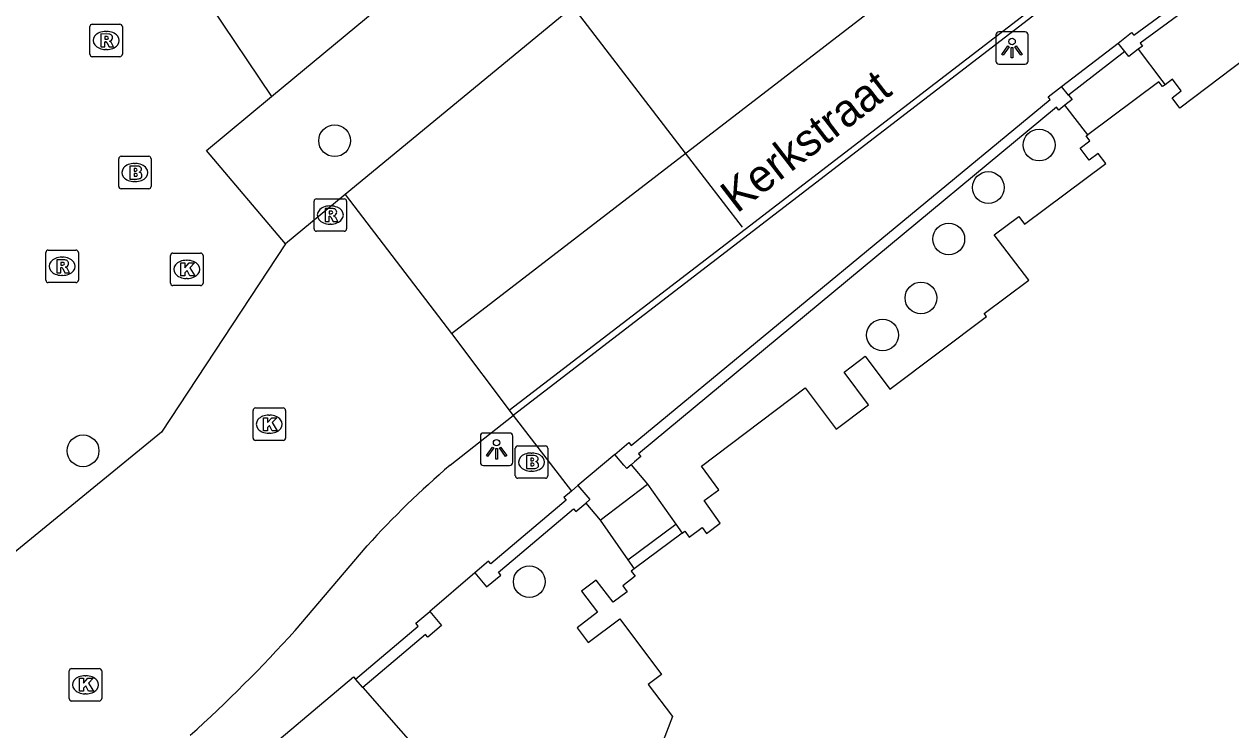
# Model space of a CAD drawing. Extents: x 161087 to 161922, y 382574 to 383873.
# Drawn here: x 161349.71 to 161386.87, y 383087.66 to 383109.41 of the extents above; entities that cross this region are included whole.
import ezdxf

# ---------------------------------------------------------------- set-up
doc = ezdxf.new("R2010")
doc.units = 0
for name, color, linetype in [('IMGEO_Boom', 7, 'Continuous'), ('IMGEO_Brandkraan', 7, 'Continuous'), ('IMGEO_Kolk', 7, 'Continuous'), ('IMGEO_Lichtpunt', 7, 'Continuous'), ('IMGEO_Lijnafwatering', 7, 'Continuous'), ('IMGEO_Muur', 7, 'Continuous'), ('IMGEO_Openbare_ruimte_label', 7, 'Continuous'), ('IMGEO_Pand', 7, 'Continuous'), ('IMGEO_Rijbaan_lokaal_open', 7, 'Continuous'), ('IMGEO_Rioolput', 7, 'Continuous'), ('IMGEO_Voetgangersgebied_open', 7, 'Continuous'), ('IMGEO_Voetpad_op_trap', 7, 'Continuous'), ('IMGEO_Voetpad_open', 7, 'Continuous')]:
    doc.layers.add(name, color=color, linetype=linetype)

msp = doc.modelspace()

# ---------------------------------------------------------------- linework, layer by layer
at = {"layer": 'IMGEO_Boom'}
for centre in [(161359.269, 383105.813), (161380.968, 383105.681), (161379.403, 383104.373), (161378.185, 383102.786), (161377.328, 383100.971), (161376.145, 383099.827), (161351.524, 383096.259), (161365.266, 383092.226)]:
    msp.add_circle(centre, 0.489, dxfattribs=at)
at = {"layer": 'IMGEO_Brandkraan'}
for p, q in [((161352.62, 383104.409), (161352.62, 383105.261)), ((161352.695, 383105.335), (161353.547, 383105.335)), ((161353.621, 383105.261), (161353.621, 383104.409)), ((161353.108, 383105.115), (161353.133, 383105.115)), ((161353.131, 383104.555), (161353.106, 383104.555)), ((161353.547, 383104.335), (161352.695, 383104.335)), ((161364.836, 383095.486), (161364.836, 383096.338)), ((161364.911, 383096.412), (161365.763, 383096.412)), ((161365.837, 383096.338), (161365.837, 383095.486)), ((161365.324, 383096.192), (161365.349, 383096.192)), ((161365.347, 383095.632), (161365.322, 383095.632)), ((161365.763, 383095.412), (161364.911, 383095.412))]:
    msp.add_line(p, q, dxfattribs=at)
for points in [[(161352.62, 383104.409), (161352.62, 383105.261)], [(161352.695, 383105.335), (161353.547, 383105.335)], [(161353.621, 383105.261), (161353.621, 383104.409)], [(161352.968, 383105.035), (161352.968, 383104.635), (161353.181, 383104.635)], [(161353.199, 383105.035), (161352.968, 383105.035)], [(161353.147, 383104.954), (161353.093, 383104.954), (161353.093, 383104.878)], [(161353.093, 383104.878), (161353.146, 383104.878)], [(161353.155, 383104.802), (161353.093, 383104.802), (161353.093, 383104.721)], [(161353.093, 383104.721), (161353.155, 383104.721)], [(161353.547, 383104.335), (161352.695, 383104.335)], [(161364.836, 383095.486), (161364.836, 383096.338)], [(161364.911, 383096.412), (161365.763, 383096.412)], [(161365.837, 383096.338), (161365.837, 383095.486)], [(161365.184, 383096.112), (161365.184, 383095.712), (161365.397, 383095.712)], [(161365.415, 383096.112), (161365.184, 383096.112)], [(161365.363, 383096.031), (161365.309, 383096.031), (161365.309, 383095.955)], [(161365.309, 383095.955), (161365.362, 383095.955)], [(161365.371, 383095.879), (161365.309, 383095.879), (161365.309, 383095.798)], [(161365.309, 383095.798), (161365.371, 383095.798)], [(161365.763, 383095.412), (161364.911, 383095.412)]]:
    msp.add_lwpolyline(points, dxfattribs=at)
for centre, radius, start, end in [((161352.697, 383105.259), 0.0765, 91.552, 178.448), ((161352.697, 383105.259), 0.0765, 91.552, 178.448), ((161353.545, 383105.259), 0.0765, 1.552, 88.448), ((161353.545, 383105.259), 0.0765, 1.552, 88.448), ((161353.148, 383104.916), 0.0379, 267.8285, 90.9355), ((161353.203, 383104.89), 0.145, 59.4692, 91.5367), ((161353.228, 383104.937), 0.0922, 285.5137, 58.1501), ((161353.233, 383104.745), 0.105, 301.3115, 78.989), ((161353.156, 383104.761), 0.0404, 269.8759, 90.5077), ((161353.187, 383104.886), 0.251, 268.6676, 293.5347), ((161352.697, 383104.411), 0.0765, 181.552, 268.448), ((161352.697, 383104.411), 0.0765, 181.552, 268.448), ((161353.545, 383104.411), 0.0765, 271.552, 358.448), ((161353.545, 383104.411), 0.0765, 271.552, 358.448), ((161364.913, 383096.336), 0.0765, 91.552, 178.448), ((161364.913, 383096.336), 0.0765, 91.552, 178.448), ((161365.761, 383096.336), 0.0765, 1.552, 88.448), ((161365.761, 383096.336), 0.0765, 1.552, 88.448), ((161365.364, 383095.993), 0.0379, 267.8285, 90.9355), ((161365.419, 383095.967), 0.145, 59.4692, 91.5367), ((161365.444, 383096.014), 0.0922, 285.5137, 58.1501), ((161365.449, 383095.822), 0.105, 301.3115, 78.989), ((161365.372, 383095.838), 0.0404, 269.8759, 90.5077), ((161365.403, 383095.963), 0.251, 268.6676, 293.5347), ((161364.913, 383095.488), 0.0765, 181.552, 268.448), ((161364.913, 383095.488), 0.0765, 181.552, 268.448), ((161365.761, 383095.488), 0.0765, 271.552, 358.448), ((161365.761, 383095.488), 0.0765, 271.552, 358.448)]:
    msp.add_arc(centre, radius, start, end, dxfattribs=at)
for centre, major_axis, ratio, start_param, end_param in [((161353.107, 383104.835), (-0.387, 0.002), 0.722429, 4.712389, 7.853982), ((161353.132, 383104.835), (-0.39, 0.002), 0.717154, 1.570796, 4.712389), ((161365.323, 383095.912), (-0.387, 0.002), 0.722429, 4.712389, 7.853982), ((161365.348, 383095.912), (-0.39, 0.002), 0.717154, 1.570796, 4.712389)]:
    msp.add_ellipse(centre, major_axis=major_axis, ratio=ratio, start_param=start_param, end_param=end_param, dxfattribs=at)
at = {"layer": 'IMGEO_Kolk'}
for p, q in [((161354.217, 383101.425), (161354.217, 383102.277)), ((161354.292, 383102.351), (161355.144, 383102.351)), ((161355.218, 383102.277), (161355.218, 383101.425)), ((161354.705, 383102.131), (161354.73, 383102.131)), ((161354.728, 383101.571), (161354.703, 383101.571)), ((161355.144, 383101.351), (161354.292, 383101.351)), ((161356.758, 383096.653), (161356.758, 383097.505)), ((161356.833, 383097.579), (161357.685, 383097.579)), ((161357.759, 383097.505), (161357.759, 383096.653)), ((161357.246, 383097.359), (161357.271, 383097.359)), ((161357.269, 383096.799), (161357.244, 383096.799)), ((161357.685, 383096.579), (161356.833, 383096.579)), ((161351.096, 383088.623), (161351.096, 383089.475)), ((161351.171, 383089.549), (161352.023, 383089.549)), ((161351.584, 383089.329), (161351.609, 383089.329)), ((161352.097, 383089.475), (161352.097, 383088.623)), ((161352.023, 383088.549), (161351.171, 383088.549)), ((161351.607, 383088.769), (161351.582, 383088.769))]:
    msp.add_line(p, q, dxfattribs=at)
for points in [[(161354.217, 383101.425), (161354.217, 383102.277)], [(161354.292, 383102.351), (161355.144, 383102.351)], [(161355.218, 383102.277), (161355.218, 383101.425)], [(161354.538, 383102.051), (161354.661, 383102.051), (161354.661, 383101.9), (161354.791, 383102.051), (161354.955, 383102.051), (161354.809, 383101.9), (161354.962, 383101.651), (161354.81, 383101.651), (161354.725, 383101.815), (161354.661, 383101.748), (161354.661, 383101.651), (161354.538, 383101.651), (161354.538, 383102.051)], [(161355.144, 383101.351), (161354.292, 383101.351)], [(161356.758, 383096.653), (161356.758, 383097.505)], [(161356.833, 383097.579), (161357.685, 383097.579)], [(161357.759, 383097.505), (161357.759, 383096.653)], [(161357.079, 383097.279), (161357.202, 383097.279), (161357.202, 383097.128), (161357.332, 383097.279), (161357.496, 383097.279), (161357.35, 383097.128), (161357.503, 383096.879), (161357.351, 383096.879), (161357.266, 383097.043), (161357.202, 383096.976), (161357.202, 383096.879), (161357.079, 383096.879), (161357.079, 383097.279)], [(161357.685, 383096.579), (161356.833, 383096.579)], [(161351.096, 383088.623), (161351.096, 383089.475)], [(161351.171, 383089.549), (161352.023, 383089.549)], [(161351.417, 383089.249), (161351.54, 383089.249), (161351.54, 383089.098), (161351.67, 383089.249), (161351.834, 383089.249), (161351.688, 383089.098), (161351.841, 383088.849), (161351.689, 383088.849), (161351.604, 383089.013), (161351.54, 383088.946), (161351.54, 383088.849), (161351.417, 383088.849), (161351.417, 383089.249)], [(161352.097, 383089.475), (161352.097, 383088.623)], [(161352.023, 383088.549), (161351.171, 383088.549)]]:
    msp.add_lwpolyline(points, dxfattribs=at)
for centre, start, end in [((161354.294, 383102.275), 91.552, 178.448), ((161354.294, 383102.275), 91.552, 178.448), ((161355.142, 383102.275), 1.552, 88.448), ((161355.142, 383102.275), 1.552, 88.448), ((161354.294, 383101.427), 181.552, 268.448), ((161354.294, 383101.427), 181.552, 268.448), ((161355.142, 383101.427), 271.552, 358.448), ((161355.142, 383101.427), 271.552, 358.448), ((161356.835, 383097.503), 91.552, 178.448), ((161356.835, 383097.503), 91.552, 178.448), ((161357.683, 383097.503), 1.552, 88.448), ((161357.683, 383097.503), 1.552, 88.448), ((161356.835, 383096.655), 181.552, 268.448), ((161356.835, 383096.655), 181.552, 268.448), ((161357.683, 383096.655), 271.552, 358.448), ((161357.683, 383096.655), 271.552, 358.448), ((161351.173, 383089.473), 91.552, 178.448), ((161351.173, 383089.473), 91.552, 178.448), ((161352.021, 383089.473), 1.552, 88.448), ((161352.021, 383089.473), 1.552, 88.448), ((161351.173, 383088.625), 181.552, 268.448), ((161351.173, 383088.625), 181.552, 268.448), ((161352.021, 383088.625), 271.552, 358.448), ((161352.021, 383088.625), 271.552, 358.448)]:
    msp.add_arc(centre, 0.0765, start, end, dxfattribs=at)
for centre, major_axis, ratio, start_param, end_param in [((161354.704, 383101.851), (-0.387, 0.002), 0.722429, 4.712389, 7.853982), ((161354.729, 383101.851), (-0.39, 0.002), 0.717154, 1.570796, 4.712389), ((161357.245, 383097.079), (-0.387, 0.002), 0.722429, 4.712389, 7.853982), ((161357.27, 383097.079), (-0.39, 0.002), 0.717154, 1.570796, 4.712389), ((161351.583, 383089.049), (-0.387, 0.002), 0.722429, 4.712389, 7.853982), ((161351.608, 383089.049), (-0.39, 0.002), 0.717154, 1.570796, 4.712389)]:
    msp.add_ellipse(centre, major_axis=major_axis, ratio=ratio, start_param=start_param, end_param=end_param, dxfattribs=at)
at = {"layer": 'IMGEO_Lichtpunt'}
for p, q in [((161379.634, 383109.075), (161379.634, 383108.268)), ((161379.634, 383109.075), (161379.634, 383108.268)), ((161380.536, 383109.17), (161379.728, 383109.17)), ((161380.536, 383109.17), (161379.728, 383109.17)), ((161380.63, 383108.268), (161380.63, 383109.075)), ((161380.63, 383108.268), (161380.63, 383109.075)), ((161379.728, 383108.174), (161380.536, 383108.174)), ((161379.728, 383108.174), (161380.536, 383108.174)), ((161363.759, 383096.712), (161363.759, 383095.905)), ((161363.759, 383096.712), (161363.759, 383095.905)), ((161364.661, 383096.807), (161363.853, 383096.807)), ((161364.661, 383096.807), (161363.853, 383096.807)), ((161364.755, 383095.905), (161364.755, 383096.712)), ((161364.755, 383095.905), (161364.755, 383096.712)), ((161363.853, 383095.811), (161364.661, 383095.811)), ((161363.853, 383095.811), (161364.661, 383095.811))]:
    msp.add_line(p, q, dxfattribs=at)
for points in [[(161380.008, 383108.739), (161380.047, 383108.711), (161379.859, 383108.449), (161379.821, 383108.476), (161380.008, 383108.739)], [(161380.11, 383108.691), (161380.157, 383108.691), (161380.157, 383108.369), (161380.11, 383108.369), (161380.11, 383108.691)], [(161380.22, 383108.711), (161380.258, 383108.738), (161380.445, 383108.476), (161380.406, 383108.448), (161380.22, 383108.711)], [(161364.133, 383096.376), (161364.172, 383096.348), (161363.984, 383096.086), (161363.946, 383096.113), (161364.133, 383096.376)], [(161364.235, 383096.328), (161364.282, 383096.328), (161364.282, 383096.006), (161364.235, 383096.006), (161364.235, 383096.328)], [(161364.345, 383096.348), (161364.383, 383096.375), (161364.57, 383096.113), (161364.531, 383096.085), (161364.345, 383096.348)]]:
    msp.add_lwpolyline(points, dxfattribs=at)
for centre in [(161380.133, 383108.873), (161364.258, 383096.51)]:
    msp.add_circle(centre, 0.0994, dxfattribs=at)
for centre, start, end in [((161379.728, 383109.075), 90, 180), ((161379.728, 383109.075), 90, 180), ((161380.536, 383109.075), 0, 90), ((161380.536, 383109.075), 0, 90), ((161379.728, 383108.268), 180, 270), ((161379.728, 383108.268), 180, 270), ((161380.536, 383108.268), 270, 0), ((161380.536, 383108.268), 270, 360), ((161363.853, 383096.712), 90, 180), ((161363.853, 383096.712), 90, 180), ((161364.661, 383096.712), 0, 90), ((161364.661, 383096.712), 0, 90), ((161363.853, 383095.905), 180, 270), ((161363.853, 383095.905), 180, 270), ((161364.661, 383095.905), 270, 0), ((161364.661, 383095.905), 270, 360)]:
    msp.add_arc(centre, 0.0946, start, end, dxfattribs=at)
at = {"layer": 'IMGEO_Lijnafwatering'}
for points in [[(161371.911, 383103.092), (161386.413, 383114.242)], [(161371.832, 383103.147), (161370.078, 383105.431), (161366.613, 383109.945)], [(161364.65, 383097.51), (161371.911, 383103.092)]]:
    msp.add_lwpolyline(points, dxfattribs=at)
at = {"layer": 'IMGEO_Muur'}
for points in [[(161383.403, 383108.826), (161383.816, 383109.153), (161383.887, 383109.068), (161387.88, 383112.004), (161395.4, 383117.308), (161399.385, 383120.025), (161404.347, 383123.179), (161413.367, 383127.97), (161413.315, 383128.067), (161413.877, 383128.367)], [(161415.27, 383125.521), (161413.802, 383127.485), (161413.669, 383127.408), (161413.514, 383127.686), (161410.831, 383126.299), (161404.509, 383122.902), (161399.561, 383119.758), (161395.582, 383117.045), (161388.067, 383111.744), (161384.079, 383108.819), (161384.146, 383108.732), (161384.022, 383108.636)], [(161383.604, 383108.566), (161383.403, 383108.826)], [(161384.022, 383108.636), (161383.727, 383108.407), (161383.604, 383108.566)], [(161367.896, 383096.148), (161368.328, 383096.515), (161368.405, 383096.423), (161381.312, 383107.086), (161381.249, 383107.167), (161381.659, 383107.49)], [(161381.872, 383107.22), (161381.659, 383107.49)], [(161381.872, 383107.22), (161381.981, 383107.081), (161381.761, 383106.908)], [(161381.761, 383106.908), (161381.572, 383106.759), (161381.504, 383106.846), (161368.628, 383096.166), (161368.699, 383096.083), (161368.507, 383095.919), (161368.402, 383095.83)], [(161368.402, 383095.83), (161368.265, 383095.714), (161368.174, 383095.82), (161367.896, 383096.148)], [(161366.565, 383095.02), (161366.762, 383095.189)], [(161366.762, 383095.189), (161367.133, 383094.756), (161367.004, 383094.645)], [(161366.565, 383095.02), (161366.332, 383094.821), (161366.403, 383094.737), (161364.081, 383092.776), (161364.011, 383092.86), (161363.584, 383092.504)], [(161363.584, 383092.504), (161363.949, 383092.066), (161364.387, 383092.431), (161364.316, 383092.516), (161364.774, 383092.903), (161366.628, 383094.469), (161366.7, 383094.385), (161367.004, 383094.645)], [(161359.918, 383089.219), (161361.847, 383090.86), (161361.775, 383090.944), (161362.202, 383091.306)], [(161362.202, 383091.306), (161362.565, 383090.88), (161362.138, 383090.517), (161362.067, 383090.601), (161360.142, 383088.963)]]:
    msp.add_lwpolyline(points, dxfattribs=at)
at = {"layer": 'IMGEO_Pand'}
for points in [[(161387.786, 383108.696), (161385.304, 383106.822), (161385.063, 383107.141), (161385.342, 383107.352), (161385.071, 383107.711), (161384.844, 383107.54)], [(161384.844, 383107.54), (161384.768, 383107.482), (161384.653, 383107.634), (161382.467, 383105.997)], [(161369.977, 383093.725), (161370.057, 383093.785), (161370.194, 383093.6), (161370.587, 383093.893), (161370.724, 383093.709), (161371.149, 383094.025), (161370.654, 383094.729), (161371.102, 383095.062), (161370.566, 383095.785), (161373.763, 383098.201), (161374.717, 383096.929), (161375.717, 383097.678), (161374.962, 383098.687), (161375.61, 383099.172), (161376.365, 383098.164), (161379.342, 383100.395), (161379.273, 383100.486), (161380.648, 383101.52), (161379.581, 383102.912), (161380.342, 383103.481), (161380.522, 383103.241), (161383.019, 383105.111), (161382.785, 383105.424), (161382.505, 383105.214), (161382.23, 383105.582), (161382.534, 383105.81), (161382.42, 383105.962), (161382.467, 383105.997)], [(161369.977, 383093.725), (161368.493, 383092.62)], [(161368.493, 383092.62), (161368.405, 383092.554), (161368.527, 383092.399), (161368.142, 383092.096), (161368.281, 383091.917), (161367.846, 383091.591), (161367.327, 383092.276), (161366.873, 383091.931), (161367.362, 383091.286), (161366.739, 383090.806), (161367.084, 383090.355), (161368.053, 383091.086), (161369.34, 383089.364), (161368.932, 383089.059), (161369.672, 383088.069), (161367.615, 383082.684)], [(161354.318, 383084.62), (161354.364, 383084.66), (161359.849, 383089.298), (161359.918, 383089.219)], [(161360.142, 383088.963), (161359.918, 383089.219)], [(161360.142, 383088.963), (161363.648, 383084.959), (161362.972, 383084.424), (161361.312, 383083.146), (161362.666, 383081.388), (161363.693, 383080.054), (161361.831, 383078.62), (161365.218, 383074.222), (161364.102, 383073.291)]]:
    msp.add_lwpolyline(points, dxfattribs=at)
at = {"layer": 'IMGEO_Rijbaan_lokaal_open'}
for points in [[(161359.598, 383104.154), (161357.76, 383102.637)], [(161359.598, 383104.154), (161362.866, 383099.876)], [(161357.76, 383102.637), (161353.934, 383096.833), (161331.379, 383078.376), (161324.754, 383073.591), (161319.89, 383069.645)], [(161362.866, 383099.876), (161364.77, 383097.35)], [(161362.829, 383095.814), (161364.77, 383097.35)], [(161358.051, 383090.722), (161360.276, 383093.328)]]:
    msp.add_lwpolyline(points, dxfattribs=at)
for centre, radius, start, end in [((161379.428, 383076.213), 25.685, 130.2606, 138.2159), ((161326.347, 383119.226), 42.634, 311.9039, 318.0429)]:
    msp.add_arc(centre, radius, start, end, dxfattribs=at)
at = {"layer": 'IMGEO_Rioolput'}
for p, q in [((161351.733, 383108.478), (161351.733, 383109.33)), ((161351.808, 383109.404), (161352.66, 383109.404)), ((161352.734, 383109.33), (161352.734, 383108.478)), ((161352.221, 383109.184), (161352.246, 383109.184)), ((161352.244, 383108.624), (161352.219, 383108.624)), ((161352.66, 383108.404), (161351.808, 383108.404)), ((161358.638, 383103.099), (161358.638, 383103.951)), ((161358.713, 383104.025), (161359.565, 383104.025)), ((161359.126, 383103.805), (161359.151, 383103.805)), ((161359.639, 383103.951), (161359.639, 383103.099)), ((161359.565, 383103.025), (161358.713, 383103.025)), ((161359.149, 383103.245), (161359.124, 383103.245)), ((161350.377, 383101.519), (161350.377, 383102.371)), ((161350.452, 383102.445), (161351.304, 383102.445)), ((161350.865, 383102.225), (161350.89, 383102.225)), ((161351.378, 383102.371), (161351.378, 383101.519)), ((161350.888, 383101.665), (161350.863, 383101.665)), ((161351.304, 383101.445), (161350.452, 383101.445))]:
    msp.add_line(p, q, dxfattribs=at)
for points in [[(161351.733, 383108.478), (161351.733, 383109.33)], [(161351.808, 383109.404), (161352.66, 383109.404)], [(161352.734, 383109.33), (161352.734, 383108.478)], [(161352.322, 383109.102), (161352.07, 383109.104), (161352.07, 383108.704)], [(161352.248, 383109.023), (161352.194, 383109.023), (161352.194, 383108.942)], [(161352.194, 383108.942), (161352.246, 383108.942)], [(161352.07, 383108.704), (161352.194, 383108.704), (161352.194, 383108.866), (161352.205, 383108.866)], [(161352.252, 383108.837), (161352.323, 383108.704), (161352.463, 383108.704), (161352.398, 383108.83)], [(161352.66, 383108.404), (161351.808, 383108.404)], [(161358.638, 383103.099), (161358.638, 383103.951)], [(161358.713, 383104.025), (161359.565, 383104.025)], [(161359.227, 383103.723), (161358.975, 383103.725), (161358.975, 383103.325)], [(161359.639, 383103.951), (161359.639, 383103.099)], [(161358.975, 383103.325), (161359.099, 383103.325), (161359.099, 383103.487), (161359.11, 383103.487)], [(161359.153, 383103.644), (161359.099, 383103.644), (161359.099, 383103.563)], [(161359.099, 383103.563), (161359.151, 383103.563)], [(161359.157, 383103.458), (161359.228, 383103.325), (161359.368, 383103.325), (161359.303, 383103.451)], [(161359.565, 383103.025), (161358.713, 383103.025)], [(161350.377, 383101.519), (161350.377, 383102.371)], [(161350.452, 383102.445), (161351.304, 383102.445)], [(161351.378, 383102.371), (161351.378, 383101.519)], [(161350.966, 383102.143), (161350.714, 383102.145), (161350.714, 383101.745)], [(161350.714, 383101.745), (161350.838, 383101.745), (161350.838, 383101.907), (161350.849, 383101.907)], [(161350.892, 383102.064), (161350.838, 383102.064), (161350.838, 383101.983)], [(161350.838, 383101.983), (161350.89, 383101.983)], [(161350.896, 383101.878), (161350.967, 383101.745), (161351.107, 383101.745), (161351.042, 383101.871)], [(161351.304, 383101.445), (161350.452, 383101.445)]]:
    msp.add_lwpolyline(points, dxfattribs=at)
for centre, radius, start, end in [((161351.81, 383109.328), 0.0765, 91.552, 178.448), ((161351.81, 383109.328), 0.0765, 91.552, 178.448), ((161352.658, 383109.328), 0.0765, 1.552, 88.448), ((161352.658, 383109.328), 0.0765, 1.552, 88.448), ((161352.23, 383109.131), 0.19, 274.7715, 282.9687), ((161352.254, 383108.927), 0.0964, 77.0061, 93.1865), ((161352.268, 383108.984), 0.0378, 276.6634, 79.6772), ((161352.321, 383108.992), 0.109, 350.3612, 89.416), ((161352.319, 383108.992), 0.112, 277.5842, 350.9817), ((161352.204, 383108.813), 0.0533, 26.0293, 88.6989), ((161352.303, 383108.777), 0.108, 29.5134, 73.7905), ((161351.81, 383108.48), 0.0765, 181.552, 268.448), ((161351.81, 383108.48), 0.0765, 181.552, 268.448), ((161352.658, 383108.48), 0.0765, 271.552, 358.448), ((161352.658, 383108.48), 0.0765, 271.552, 358.448), ((161358.715, 383103.949), 0.0765, 91.552, 178.448), ((161358.715, 383103.949), 0.0765, 91.552, 178.448), ((161359.226, 383103.613), 0.109, 350.3612, 89.416), ((161359.563, 383103.949), 0.0765, 1.552, 88.448), ((161359.563, 383103.949), 0.0765, 1.552, 88.448), ((161359.109, 383103.434), 0.0533, 26.0293, 88.6989), ((161359.135, 383103.752), 0.19, 274.7715, 282.9687), ((161359.159, 383103.548), 0.0964, 77.0061, 93.1865), ((161359.173, 383103.605), 0.0378, 276.6634, 79.6772), ((161359.224, 383103.613), 0.112, 277.5842, 350.9817), ((161359.208, 383103.398), 0.108, 29.5134, 73.7905), ((161358.715, 383103.101), 0.0765, 181.552, 268.448), ((161358.715, 383103.101), 0.0765, 181.552, 268.448), ((161359.563, 383103.101), 0.0765, 271.552, 358.448), ((161359.563, 383103.101), 0.0765, 271.552, 358.448), ((161350.454, 383102.369), 0.0765, 91.552, 178.448), ((161350.454, 383102.369), 0.0765, 91.552, 178.448), ((161351.302, 383102.369), 0.0765, 1.552, 88.448), ((161351.302, 383102.369), 0.0765, 1.552, 88.448), ((161350.848, 383101.854), 0.0533, 26.0293, 88.6989), ((161350.874, 383102.172), 0.19, 274.7715, 282.9687), ((161350.898, 383101.968), 0.0964, 77.0061, 93.1865), ((161350.912, 383102.025), 0.0378, 276.6634, 79.6772), ((161350.965, 383102.033), 0.109, 350.3612, 89.416), ((161350.963, 383102.033), 0.112, 277.5842, 350.9817), ((161350.947, 383101.818), 0.108, 29.5134, 73.7905), ((161350.454, 383101.521), 0.0765, 181.552, 268.448), ((161350.454, 383101.521), 0.0765, 181.552, 268.448), ((161351.302, 383101.521), 0.0765, 271.552, 358.448), ((161351.302, 383101.521), 0.0765, 271.552, 358.448)]:
    msp.add_arc(centre, radius, start, end, dxfattribs=at)
for centre, major_axis, ratio, start_param, end_param in [((161352.22, 383108.904), (-0.387, 0.002), 0.722429, 4.712389, 7.853982), ((161352.245, 383108.904), (-0.39, 0.002), 0.717154, 1.570796, 4.712389), ((161359.125, 383103.525), (-0.387, 0.002), 0.722429, 4.712389, 7.853982), ((161359.15, 383103.525), (-0.39, 0.002), 0.717154, 1.570796, 4.712389), ((161350.864, 383101.945), (-0.387, 0.002), 0.722429, 4.712389, 7.853982), ((161350.889, 383101.945), (-0.39, 0.002), 0.717154, 1.570796, 4.712389)]:
    msp.add_ellipse(centre, major_axis=major_axis, ratio=ratio, start_param=start_param, end_param=end_param, dxfattribs=at)
at = {"layer": 'IMGEO_Voetgangersgebied_open'}
for points in [[(161362.866, 383099.876), (161421.439, 383144.995)], [(161410.626, 383132.608), (161409.678, 383131.89), (161364.77, 383097.35)], [(161357.325, 383107.176), (161368.972, 383116.831), (161371.397, 383113.893), (161359.598, 383104.154)], [(161353.567, 383112.777), (161357.325, 383107.176)], [(161357.76, 383102.637), (161355.325, 383105.517), (161357.325, 383107.176)]]:
    msp.add_lwpolyline(points, dxfattribs=at)
at = {"layer": 'IMGEO_Voetpad_op_trap'}
for points in [[(161384.022, 383108.636), (161384.745, 383107.674), (161384.844, 383107.54)], [(161382.467, 383105.997), (161381.761, 383106.908)], [(161368.908, 383095.236), (161369.78, 383094.003)], [(161367.451, 383094.12), (161368.299, 383092.899)]]:
    msp.add_lwpolyline(points, dxfattribs=at)
at = {"layer": 'IMGEO_Voetpad_open'}
for points in [[(161381.659, 383107.49), (161383.403, 383108.826)], [(161383.604, 383108.566), (161381.872, 383107.22)], [(161364.77, 383097.35), (161366.565, 383095.02)], [(161367.896, 383096.148), (161366.762, 383095.189)], [(161368.402, 383095.83), (161368.908, 383095.236)], [(161367.451, 383094.12), (161368.908, 383095.236)], [(161367.004, 383094.645), (161367.451, 383094.12)], [(161368.299, 383092.899), (161369.78, 383094.003)], [(161369.78, 383094.003), (161369.977, 383093.725)], [(161368.299, 383092.899), (161368.493, 383092.62)], [(161363.584, 383092.504), (161362.202, 383091.306)]]:
    msp.add_lwpolyline(points, dxfattribs=at)

# ---------------------------------------------------------------- texts
at = {"layer": 'IMGEO_Openbare_ruimte_label'}
msp.add_text('Kerkstraat', height=1, rotation=37.5686, dxfattribs=at).set_placement((161371.661, 383103.559))

doc.saveas('drawing.dxf')
